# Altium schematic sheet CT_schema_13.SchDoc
size 391 x 385 mm
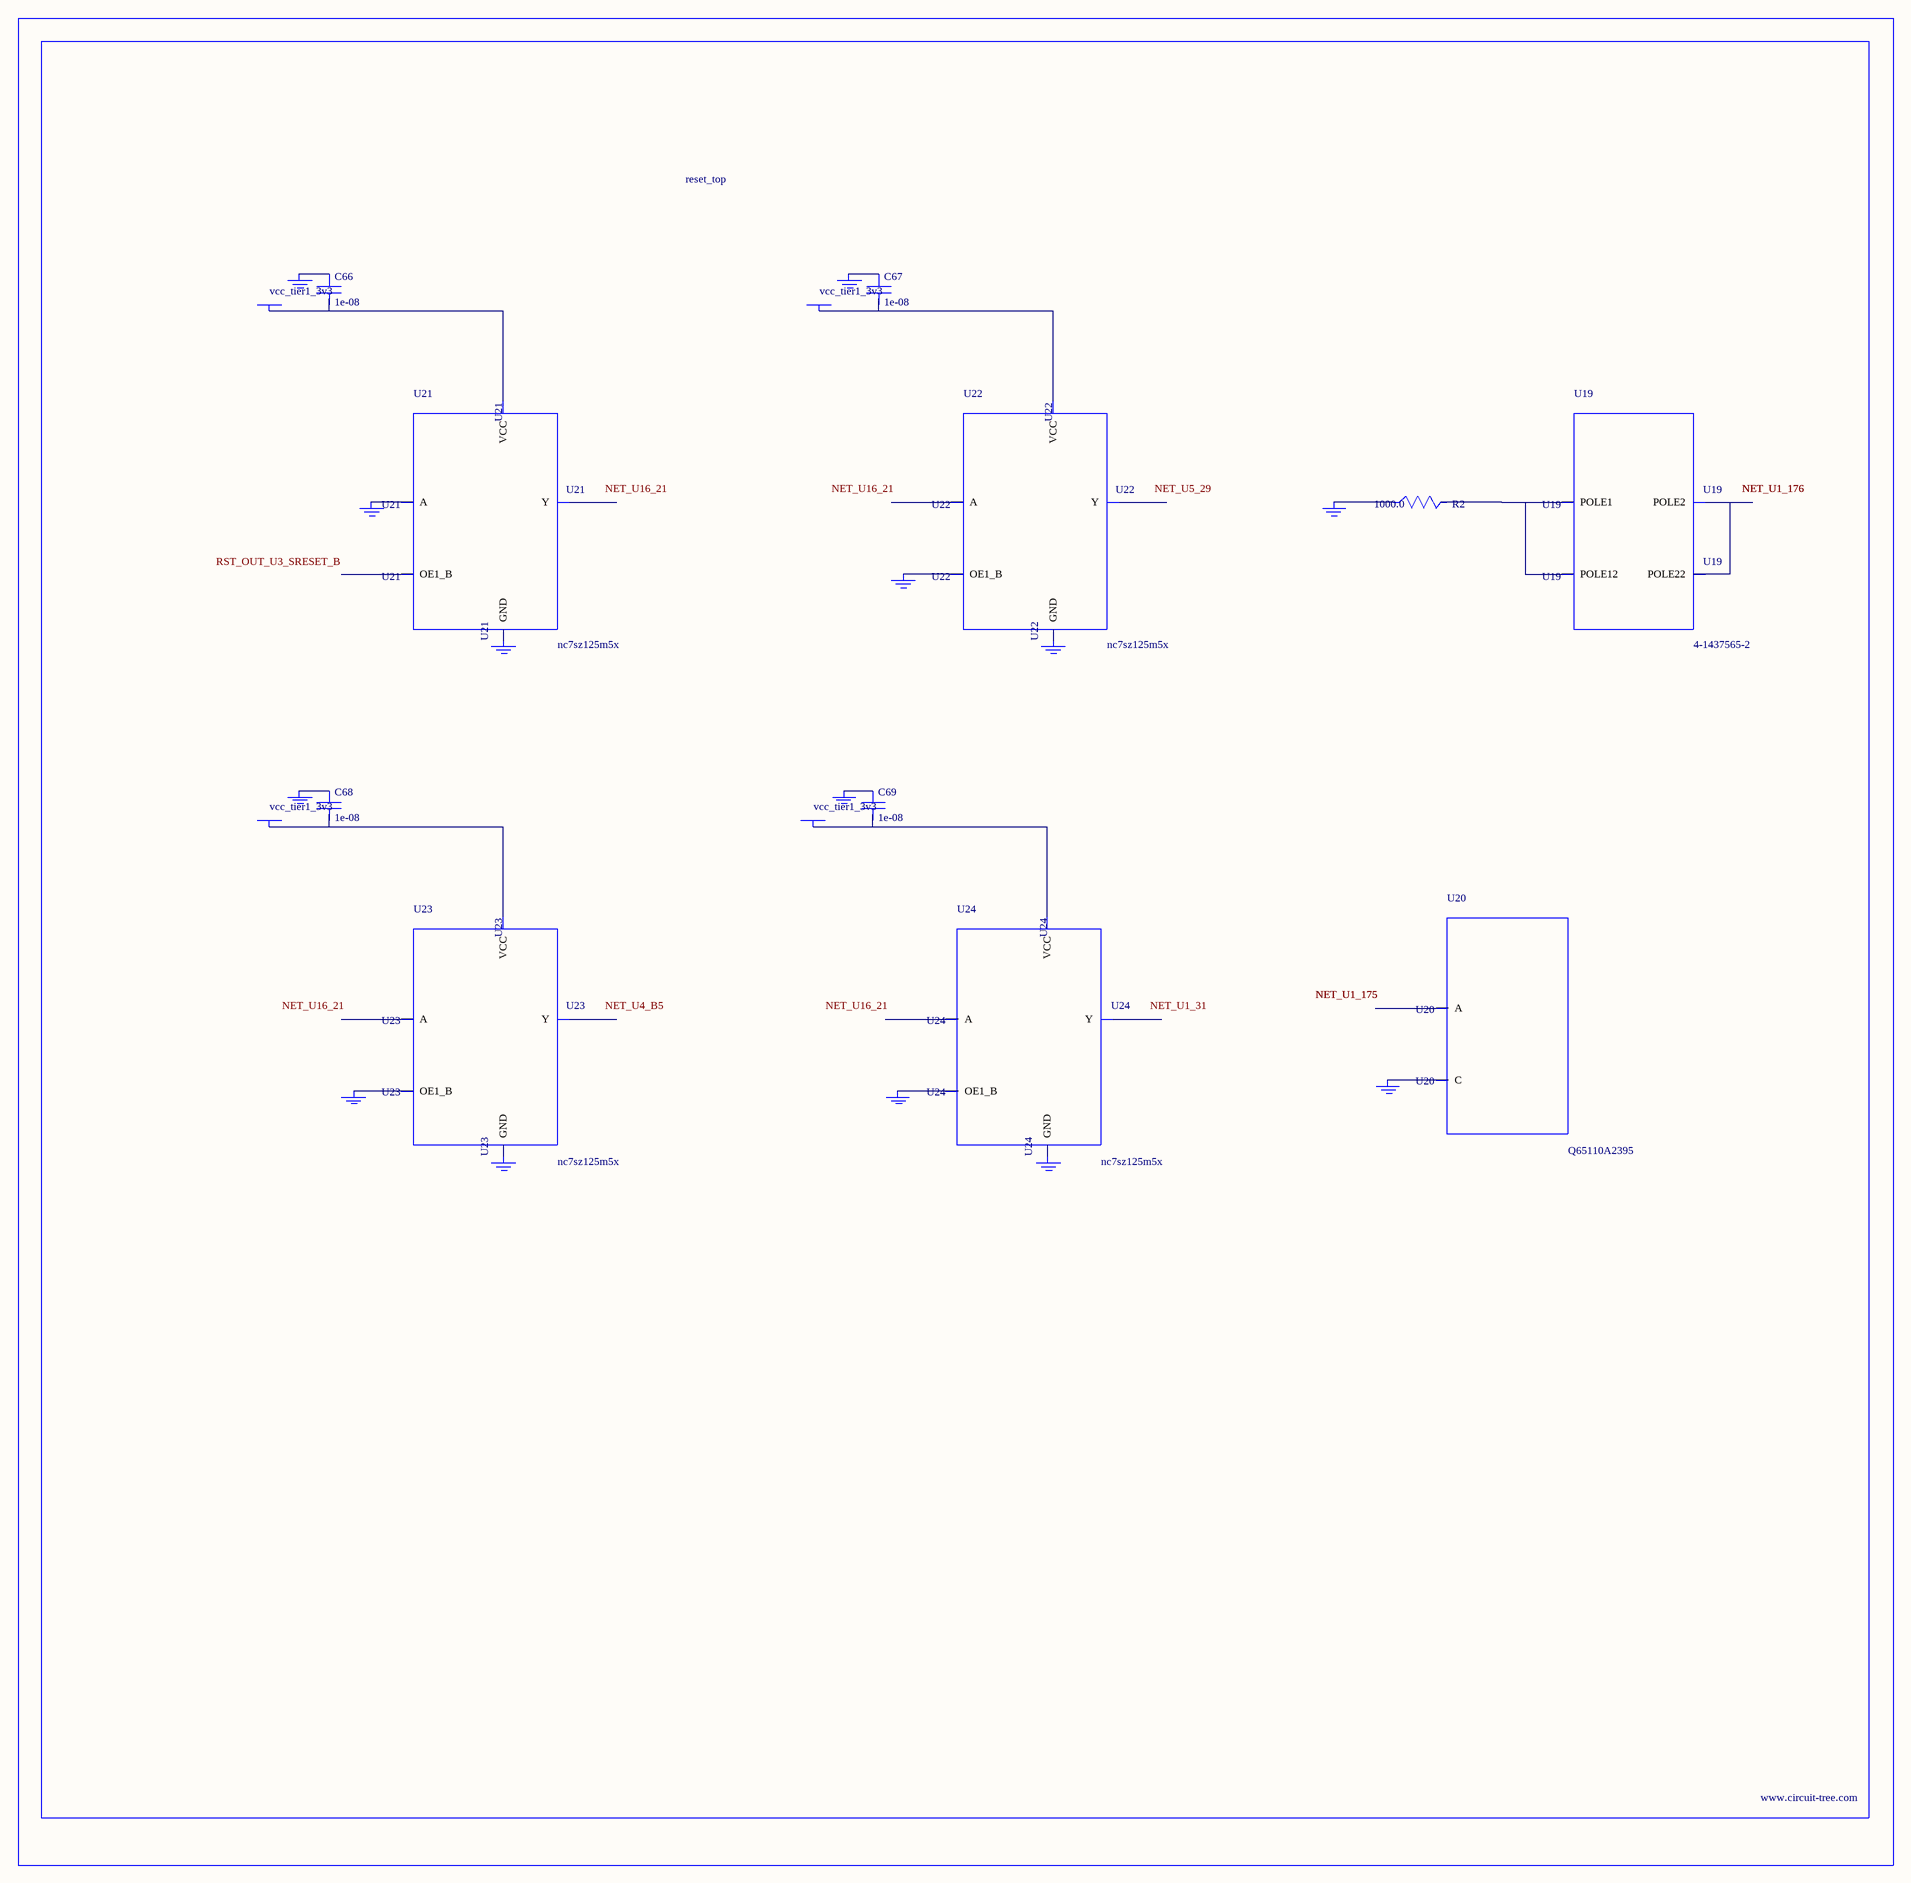
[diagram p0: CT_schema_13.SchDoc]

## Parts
BORDER12  (no value)
C66  1e-08  [C0402]
C67  1e-08  [C0402]
C68  1e-08  [C0402]
C69  1e-08  [C0402]
GND_INSTANCE_12_0  (no value)
GND_INSTANCE_12_1  (no value)
GND_INSTANCE_12_2  (no value)
GND_INSTANCE_12_3  (no value)
GND_INSTANCE_12_4  (no value)
GND_INSTANCE_12_5  (no value)
GND_INSTANCE_12_6  (no value)
GND_INSTANCE_12_7  (no value)
GND_INSTANCE_12_8  (no value)
GND_INSTANCE_12_9  (no value)
GND_INSTANCE_12_10  (no value)
GND_INSTANCE_12_11  (no value)
GND_INSTANCE_12_12  (no value)
GND_INSTANCE_12_13  (no value)
POWER_INSTANCE_12_0  vcc_tier1_3v3
POWER_INSTANCE_12_1  vcc_tier1_3v3
POWER_INSTANCE_12_2  vcc_tier1_3v3
POWER_INSTANCE_12_3  vcc_tier1_3v3
R2  1000.0  [R0603]
U19  4-1437565-2  [SW_4-1437565-2]
U20  Q65110A2395  [LGM67K-G1J2-24-Z]
U21  nc7sz125m5x  [NC7SZ125M5X]
U22  nc7sz125m5x  [NC7SZ125M5X]
U23  nc7sz125m5x  [NC7SZ125M5X]
U24  nc7sz125m5x  [NC7SZ125M5X]

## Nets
NetC66_1: C66.1 GND_INSTANCE_12_2.0(GND)
NetC66_2: C66.2 POWER_INSTANCE_12_0.0(PWR) U21.5(VCC)
NetC67_1: C67.1 GND_INSTANCE_12_5.0(GND)
NetC67_2: C67.2 POWER_INSTANCE_12_1.0(PWR) U22.5(VCC)
NetC68_1: C68.1 GND_INSTANCE_12_8.0(GND)
NetC68_2: C68.2 POWER_INSTANCE_12_2.0(PWR) U23.5(VCC)
NetC69_1: C69.1 GND_INSTANCE_12_11.0(GND)
NetC69_2: C69.2 POWER_INSTANCE_12_3.0(PWR) U24.5(VCC)
NetGND_INSTANCE_12_0_0: GND_INSTANCE_12_0.0(GND) R2.1
NetGND_INSTANCE_12_1_0: GND_INSTANCE_12_1.0(GND) U20.C
NetGND_INSTANCE_12_3_0: GND_INSTANCE_12_3.0(GND) U21.2(A)
NetGND_INSTANCE_12_4_0: GND_INSTANCE_12_4.0(GND) U21.3(GND)
NetGND_INSTANCE_12_6_0: GND_INSTANCE_12_6.0(GND) U22.1(OE1_B)
NetGND_INSTANCE_12_7_0: GND_INSTANCE_12_7.0(GND) U22.3(GND)
NetGND_INSTANCE_12_9_0: GND_INSTANCE_12_9.0(GND) U23.1(OE1_B)
NetGND_INSTANCE_12_10_0: GND_INSTANCE_12_10.0(GND) U23.3(GND)
NetGND_INSTANCE_12_12_0: GND_INSTANCE_12_12.0(GND) U24.1(OE1_B)
NetGND_INSTANCE_12_13_0: GND_INSTANCE_12_13.0(GND) U24.3(GND)
NetR2_2: R2.2 U19.1(POLE1) U19.2(POLE12)
NetU19_3: U19.3(POLE2) U19.4(POLE22)

Not connected (* = marked no-connect by the designer): U20 A; U21 1(OE1_B) 4(Y); U22 2(A) 4(Y); U23 2(A) 4(Y); U24 2(A) 4(Y)

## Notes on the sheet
- Labels drawn without touching a wire or pin: NET_U1_31, NET_U4_B5, NET_U5_29, NET_U16_21, RST_OUT_U3_SRESET_B

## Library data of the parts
BORDER12 = BORDER_PAGE12
C66-C69 = C0402C103K3RAC
GND_INSTANCE_12_0-GND_INSTANCE_12_13 = GND
POWER_INSTANCE_12_0-POWER_INSTANCE_12_3 = PWR
R2 = RC0603JR-071KL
